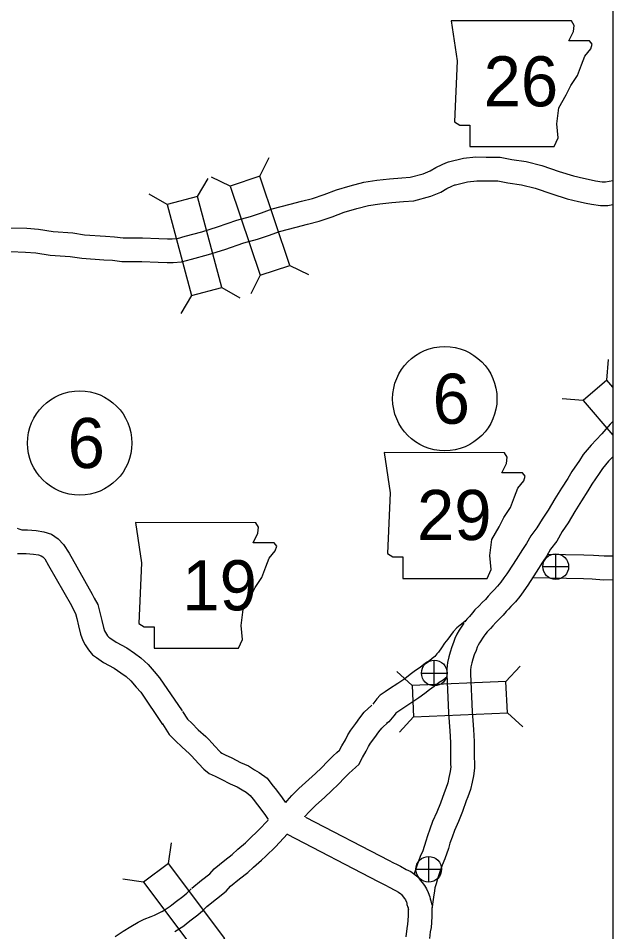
# Model space of a CAD drawing. Extents: x 79818 to 83933, y 50884 to 53307.
# Drawn here: x 81359.7 to 81460, y 53002.4 to 53156.5 of the extents above; entities that cross this region are included whole.
import ezdxf

# ---------------------------------------------------------------- set-up
doc = ezdxf.new("R2010")
doc.units = 0
for name, color, linetype in [('Level 10', 7, 'Continuous'), ('Level 20', 7, 'Continuous'), ('Level 21', 7, 'Continuous'), ('Level 26', 7, 'Continuous'), ('Level 27', 7, 'Continuous'), ('R_No Plot', 7, 'Continuous')]:
    doc.layers.add(name, color=color, linetype=linetype)

msp = doc.modelspace()

# ---------------------------------------------------------------- linework, layer by layer
at = {"layer": 'Level 10'}
for points in [[(81358.49, 53121.12), (81361.17, 53121.03), (81363.16, 53120.89), (81365.61, 53120.48), (81368.95, 53120.24), (81370.9, 53119.95), (81374.45, 53119.7), (81375.97, 53119.61), (81377.43, 53119.42), (81380.66, 53119.42), (81383.45, 53119.31), (81384.89, 53119.26), (81385.67, 53119.26), (81386.57, 53119.33), (81387.88, 53119.7), (81390.7, 53120.45), (81393.32, 53121.26), (81396.61, 53122.39), (81398.9, 53123.02), (81400.76, 53123.65), (81402.56, 53124.32), (81405.57, 53125.09), (81407.48, 53125.59), (81409.36, 53126.08), (81411.33, 53126.74), (81413.4, 53127.52), (81415.72, 53128.22), (81418, 53128.8), (81420.19, 53129.14), (81422.31, 53129.39), (81424.4, 53129.56), (81425.81, 53129.64), (81428, 53130.22), (81429.18, 53130.72), (81430.16, 53131.31), (81431.22, 53131.79), (81431.84, 53132.07), (81432.28, 53132.23), (81434.79, 53132.84), (81436.92, 53133.06), (81438.61, 53133.02), (81441, 53133.05), (81442.98, 53132.65), (81445.41, 53132.29), (81448.04, 53131.62), (81450.97, 53130.64), (81453.35, 53129.88), (81455.07, 53129.47), (81456.35, 53129.18), (81457.09, 53129.03), (81458.22, 53128.85), (81458.74, 53128.85), (81459.98, 53129.09)], [(81358.44, 53117.12), (81360.96, 53117.03), (81362.7, 53116.92), (81365.13, 53116.51), (81368.51, 53116.27), (81370.46, 53115.97), (81374.19, 53115.71), (81375.6, 53115.63), (81377.18, 53115.42), (81380.58, 53115.42), (81383.3, 53115.31), (81384.82, 53115.26), (81385.83, 53115.26), (81387.27, 53115.38), (81388.93, 53115.84), (81391.8, 53116.6), (81394.56, 53117.46), (81397.8, 53118.57), (81400.07, 53119.2), (81402.09, 53119.88), (81403.76, 53120.5), (81406.57, 53121.22), (81408.49, 53121.72), (81410.5, 53122.24), (81412.67, 53122.97), (81414.69, 53123.73), (81416.8, 53124.37), (81418.8, 53124.88), (81420.73, 53125.18), (81422.71, 53125.41), (81424.68, 53125.57), (81426.44, 53125.67), (81429.29, 53126.43), (81431, 53127.14), (81432.03, 53127.77), (81432.86, 53128.14), (81433.34, 53128.36), (81433.44, 53128.39), (81435.47, 53128.88), (81437.09, 53129.05), (81438.59, 53129.02), (81440.63, 53129.05), (81442.28, 53128.71), (81444.62, 53128.36), (81446.91, 53127.78), (81449.73, 53126.83), (81452.27, 53126.02), (81454.18, 53125.57), (81455.52, 53125.27), (81456.38, 53125.09), (81457.89, 53124.85), (81459.13, 53124.85), (81459.98, 53125.02)], [(81459.98, 53088.43), (81459.57, 53088.02), (81458.14, 53086.34), (81457.2, 53085.35), (81456.32, 53084.44), (81455.02, 53082.9), (81454.36, 53081.87), (81453.1, 53080.02), (81452.39, 53078.84), (81451.36, 53077.18), (81450.21, 53075.39), (81449.07, 53073.48), (81448.07, 53071.99), (81447.2, 53070.5), (81446.16, 53069.13), (81445.45, 53067.89), (81444.78, 53066.86), (81443.7, 53065.17)], [(81459.98, 53082.47), (81459.28, 53081.75), (81458.25, 53080.52), (81457.7, 53079.67), (81456.47, 53077.86), (81455.8, 53076.75), (81454.74, 53075.04), (81453.61, 53073.28), (81452.45, 53071.34), (81451.46, 53069.87), (81450.53, 53068.27), (81449.5, 53066.92), (81448.86, 53065.8), (81448.14, 53064.69), (81447.07, 53063.02)], [(81359.57, 53070.45), (81359.85, 53070.34), (81360.33, 53070.18), (81361.28, 53070.15), (81362.75, 53070.04), (81364.03, 53069.85), (81365.32, 53069.43), (81366.48, 53068.67), (81367.39, 53067.7), (81368.3, 53066.21), (81372.21, 53059.29), (81372.55, 53058.64), (81373.14, 53057.55), (81373.48, 53056.23), (81373.82, 53054.9), (81374.08, 53053.69), (81374.28, 53053.14), (81374.45, 53052.83), (81374.8, 53052.3), (81374.98, 53052.08), (81375.16, 53051.96), (81376.23, 53051.22), (81378.02, 53050.25), (81379.32, 53049.34), (81380.43, 53048.56), (81381.62, 53047.46), (81382.65, 53046.26), (81383.57, 53045.23), (81387.39, 53039.61)], [(81359.62, 53066.2), (81361.06, 53066.15), (81362.32, 53066.06), (81363.12, 53065.94), (81363.57, 53065.8), (81363.88, 53065.59), (81364.19, 53065.26), (81364.85, 53064.18), (81368.69, 53057.39), (81369.01, 53056.77), (81369.39, 53056.06), (81369.61, 53055.24), (81369.92, 53054), (81370.23, 53052.57), (81370.62, 53051.5), (81371, 53050.78), (81371.57, 53049.93), (81372.26, 53049.07), (81372.94, 53048.63), (81374.13, 53047.8), (81375.92, 53046.84), (81377.02, 53046.07), (81377.92, 53045.43), (81378.74, 53044.68), (81379.64, 53043.63), (81380.41, 53042.76), (81384.08, 53037.36)], [(81443.71, 53065.19), (81442.32, 53063.07), (81442.1, 53062.74), (81441.61, 53062.05), (81441.09, 53061.32), (81440.57, 53060.66), (81439.99, 53060.06), (81439.52, 53059.61), (81438.96, 53058.99), (81438.51, 53058.42), (81437.99, 53057.91), (81437.43, 53057.36), (81436.75, 53056.65), (81436.32, 53056.14), (81435.82, 53055.57), (81435.4, 53055.08), (81435.02, 53054.64)], [(81459.98, 53065.75), (81458.51, 53065.7), (81456.73, 53065.86), (81455.11, 53065.88), (81448.91, 53066.02)], [(81447.06, 53063), (81445.65, 53060.84), (81445.38, 53060.45), (81444.87, 53059.73), (81444.3, 53058.93), (81443.6, 53058.03), (81442.81, 53057.22), (81442.39, 53056.81), (81442.01, 53056.4), (81441.51, 53055.76), (81440.79, 53055.05), (81440.27, 53054.55), (81439.74, 53053.98), (81439.35, 53053.53), (81438.83, 53052.94), (81438.44, 53052.48), (81438.06, 53052.03)], [(81459.98, 53061.75), (81458.4, 53061.69), (81456.53, 53061.86), (81455.04, 53061.88), (81446.45, 53062.07)], [(81435.34, 53054.93), (81434.23, 53054.1), (81433.7, 53053.61), (81433.09, 53052.96), (81432.62, 53052.36), (81432.16, 53051.73), (81431.6, 53051.07), (81431.13, 53050.28), (81430.62, 53049.55), (81430.31, 53049.23), (81429.97, 53048.83), (81429.51, 53048.44), (81429.07, 53048.08), (81428.4, 53047.67), (81427.51, 53046.96), (81426.74, 53046.45), (81425.84, 53045.75), (81424.94, 53045.06), (81423.75, 53044.27), (81422.32, 53043.35), (81421.61, 53042.85), (81420.78, 53042.29), (81420.18, 53041.64), (81419.87, 53041.22), (81419.5, 53040.76)], [(81434.86, 53054.42), (81434.09, 53053.22), (81433.7, 53052.56), (81433.38, 53051.86), (81433.15, 53051.16), (81432.87, 53050.42), (81432.57, 53049.52), (81432.36, 53048.77), (81432.12, 53047.78), (81431.99, 53046.68), (81432, 53045.79), (81432.28, 53039.3)], [(81438.22, 53052.25), (81437.5, 53051.13), (81437.26, 53050.72), (81437.11, 53050.4), (81436.93, 53049.84), (81436.64, 53049.08), (81436.4, 53048.34), (81436.23, 53047.75), (81436.06, 53047.08), (81436, 53046.48), (81436, 53045.9), (81436.28, 53039.47)], [(81432.06, 53045.36), (81432.06, 53045.36), (81431.41, 53044.82), (81430.7, 53044.39), (81429.86, 53043.72), (81429.07, 53043.19), (81428.28, 53042.58), (81427.27, 53041.81), (81425.93, 53040.92), (81424.56, 53040.04), (81423.89, 53039.56), (81423.4, 53039.23), (81423.27, 53039.09), (81423.05, 53038.79), (81422.24, 53037.79), (81421.84, 53037.52)], [(81404.83, 53024.15), (81405.08, 53024.44), (81405.89, 53025.34), (81407.06, 53026.54), (81408.74, 53028.05), (81409.85, 53029.04), (81410.87, 53030.04), (81411.87, 53031.11), (81412.81, 53032.06), (81413.44, 53032.59), (81413.91, 53033.02), (81413.92, 53033.02), (81414.32, 53033.74), (81414.9, 53034.75), (81415.33, 53035.58), (81415.82, 53036.4), (81416.65, 53037.5), (81417.32, 53038.46), (81418.06, 53039.39), (81419.33, 53040.61)], [(81387.43, 53039.55), (81388.27, 53038.21), (81388.99, 53037.55), (81390.09, 53036.45), (81391.37, 53035.33), (81391.89, 53034.78), (81392.38, 53034.23), (81392.92, 53033.64), (81393.68, 53032.85), (81393.82, 53032.68), (81394.06, 53032.51), (81394.65, 53032.21), (81395.73, 53031.72), (81397.23, 53030.92), (81398.55, 53030.34), (81399.55, 53029.71), (81400.35, 53029.24), (81401.69, 53028.27), (81402.51, 53027.19), (81403.27, 53026.23), (81404.24, 53024.94), (81404.73, 53024.22), (81404.75, 53024.18)], [(81432.29, 53039.23), (81432.52, 53036.24), (81432.61, 53034.3), (81432.64, 53033.39), (81432.63, 53031.98), (81432.65, 53030.56), (81432.66, 53030.2), (81432.54, 53029.38), (81432.34, 53028.41), (81432.16, 53027.47), (81431.81, 53026.55), (81431.53, 53025.8), (81430.92, 53024.07), (81430.31, 53022.54), (81429.61, 53020.97), (81429.11, 53019.69), (81428.72, 53018.53), (81428.44, 53017.63), (81427.93, 53016.05), (81427.52, 53015.06), (81426.92, 53013.47), (81426.58, 53012.46), (81426.48, 53012.1)], [(81436.27, 53039.54), (81436.51, 53036.49), (81436.6, 53034.45), (81436.64, 53033.44), (81436.63, 53032.01), (81436.65, 53030.63), (81436.67, 53029.94), (81436.48, 53028.68), (81436.26, 53027.63), (81436.02, 53026.38), (81435.55, 53025.14), (81435.29, 53024.43), (81434.66, 53022.67), (81433.99, 53020.98), (81433.31, 53019.44), (81432.88, 53018.32), (81432.53, 53017.3), (81432.26, 53016.41), (81431.68, 53014.66), (81431.24, 53013.6), (81430.69, 53012.13), (81430.41, 53011.3), (81430.18, 53010.44), (81429.98, 53009.77), (81429.91, 53009.25), (81429.78, 53008.21), (81429.46, 53006.18)], [(81384.04, 53037.42), (81385.17, 53035.62), (81386.22, 53034.66), (81387.35, 53033.53), (81388.58, 53032.46), (81388.94, 53032.07), (81390.12, 53030.76), (81391.02, 53029.78), (81391.95, 53029.09), (81392.93, 53028.6), (81393.97, 53028.13), (81395.47, 53027.33), (81396.67, 53026.8), (81397.47, 53026.29), (81398.16, 53025.89), (81398.86, 53025.37), (81399.35, 53024.73), (81400.1, 53023.78), (81400.98, 53022.62), (81401.41, 53021.97), (81401.89, 53021.28)], [(81408.05, 53021.76), (81408.08, 53021.8), (81408.8, 53022.6), (81409.83, 53023.65), (81411.41, 53025.07), (81412.58, 53026.12), (81413.73, 53027.24), (81414.76, 53028.34), (81415.51, 53029.11), (81416.06, 53029.56), (81416.66, 53030.11), (81417.14, 53030.58), (81417.8, 53031.78), (81418.41, 53032.84), (81418.82, 53033.63), (81419.14, 53034.16), (81419.88, 53035.14), (81420.53, 53036.07), (81421.03, 53036.7), (81422.1, 53037.72)], [(81389.01, 53009.71), (81390.65, 53011.06), (81392.04, 53012.15), (81392.76, 53012.96), (81394.55, 53014.42), (81395.83, 53015.4), (81396.77, 53016.28), (81398.05, 53017.36), (81398.69, 53018), (81400.27, 53019.52), (81401.86, 53021.21)], [(81408.16, 53021.71), (81422.3, 53014.41), (81422.92, 53014.07), (81423.65, 53013.73), (81424.18, 53013.42), (81425.14, 53012.89), (81425.94, 53012.52), (81427.13, 53011.64), (81427.52, 53011.1), (81427.83, 53010.7), (81428.21, 53010.2), (81428.55, 53009.64), (81428.85, 53009.01), (81429.16, 53008.26), (81429.2, 53007.91), (81429.32, 53007.56), (81429.45, 53006.84)], [(81391.54, 53006.62), (81393.15, 53007.94), (81394.79, 53009.23), (81395.53, 53010.06), (81397.04, 53011.28), (81398.42, 53012.35), (81399.42, 53013.28), (81400.76, 53014.42), (81401.49, 53015.15), (81403.11, 53016.7), (81405.16, 53018.88)], [(81405.06, 53018.81), (81420.43, 53010.87), (81421.12, 53010.5), (81421.79, 53010.18), (81422.19, 53009.95), (81423.33, 53009.32), (81423.88, 53009.06), (81424.26, 53008.78), (81424.34, 53008.68), (81424.66, 53008.27), (81424.89, 53007.96), (81425.02, 53007.74), (81425.19, 53007.38), (81425.25, 53007.24), (81425.28, 53006.98), (81425.45, 53006.53), (81425.52, 53006.12)], [(81383.99, 53005.8), (81385.35, 53006.67), (81385.64, 53006.89), (81386.39, 53007.51), (81387.5, 53008.33), (81388.15, 53008.9), (81388.9, 53009.62)], [(81386.14, 53002.43), (81387.63, 53003.38), (81388.11, 53003.74), (81388.87, 53004.36), (81390.02, 53005.22), (81390.84, 53005.95), (81391.65, 53006.72)], [(81425.49, 53006.48), (81425.49, 53005.11), (81425.43, 53004.25), (81425.37, 53003.63), (81425.24, 53002.92), (81425.11, 53001.5)], [(81429.49, 53006.48), (81429.49, 53004.99), (81429.42, 53003.93), (81429.34, 53003.08), (81429.21, 53002.38), (81429.1, 53001.21)], [(81376.07, 53001.58), (81377.43, 53002.48), (81378.7, 53003.26), (81379.93, 53003.98), (81380.97, 53004.49), (81382.14, 53004.92), (81382.68, 53005.16), (81384.17, 53005.9)]]:
    msp.add_lwpolyline(points, dxfattribs=at)
at = {"layer": 'Level 20'}
for p, q in [((81400.48, 53129.8), (81402.05, 53132.95)), ((81395.48, 53128.12), (81392.32, 53129.68)), ((81389.97, 53126.38), (81391.73, 53129.43)), ((81384.86, 53125.02), (81381.82, 53126.79)), ((81405.53, 53114.78), (81408.68, 53113.22)), ((81400.52, 53113.1), (81398.96, 53109.95)), ((81388.93, 53109.72), (81387.17, 53106.67)), ((81394.04, 53111.07), (81397.08, 53109.31)), ((81458.99, 53095.41), (81459.27, 53098.92)), ((81454.97, 53091.98), (81451.47, 53092.26)), ((81441.98, 53044.58), (81444.36, 53047.18)), ((81426.16, 53043.91), (81423.57, 53046.29)), ((81442.21, 53039.31), (81444.8, 53036.93)), ((81426.38, 53038.63), (81424, 53036.04)), ((81385.06, 53013.91), (81385.56, 53017.39)), ((81380.83, 53010.74), (81377.35, 53011.24))]:
    msp.add_line(p, q, dxfattribs=at)
for points in [[(81395.48, 53128.12), (81400.52, 53113.1), (81405.53, 53114.78), (81400.48, 53129.8)], [(81394.04, 53111.07), (81389.97, 53126.38), (81384.86, 53125.02), (81388.93, 53109.72)], [(81441.98, 53044.58), (81426.16, 53043.91), (81426.38, 53038.63), (81442.21, 53039.31)], [(81394.56, 53001.23), (81385.06, 53013.91), (81380.83, 53010.74), (81390.34, 52998.06)]]:
    msp.add_lwpolyline(points, close=True, dxfattribs=at)
msp.add_lwpolyline([(81459.98, 53094.25), (81458.99, 53095.41), (81454.97, 53091.98), (81459.98, 53086.12)], dxfattribs=at)
at = {"layer": 'Level 21'}
for points in [[(81432.72, 53156.05), (81433.74, 53149.28), (81433.29, 53139.01), (81434.19, 53138.45), (81435.88, 53138.45), (81435.88, 53134.84), (81450.09, 53134.84), (81450.77, 53136.31), (81450.54, 53138.68), (81450.88, 53141.38), (81452.12, 53143.53), (81452.91, 53145.11), (81454.04, 53146.8), (81454.72, 53148.6), (81455.28, 53150.07), (81456.29, 53151.31), (81456.52, 53152.1), (81456.07, 53152.66), (81452.57, 53152.66), (81453.36, 53154.24), (81453.47, 53155.26), (81453.01, 53156.04)], [(81421.44, 53083.19), (81422.45, 53076.42), (81422, 53066.15), (81422.91, 53065.59), (81424.6, 53065.59), (81424.6, 53061.98), (81438.81, 53061.98), (81439.49, 53063.45), (81439.26, 53065.82), (81439.6, 53068.52), (81440.84, 53070.67), (81441.63, 53072.25), (81442.76, 53073.94), (81443.43, 53075.74), (81444, 53077.21), (81445.01, 53078.45), (81445.24, 53079.24), (81444.79, 53079.8), (81441.29, 53079.8), (81442.08, 53081.38), (81442.19, 53082.4), (81441.72, 53083.18)], [(81379.51, 53071.38), (81380.53, 53064.62), (81380.08, 53054.35), (81380.98, 53053.79), (81382.67, 53053.79), (81382.67, 53050.18), (81396.88, 53050.18), (81397.56, 53051.65), (81397.33, 53054.02), (81397.67, 53056.72), (81398.91, 53058.87), (81399.7, 53060.44), (81400.83, 53062.14), (81401.5, 53063.94), (81402.07, 53065.41), (81403.08, 53066.65), (81403.31, 53067.44), (81402.86, 53068), (81399.36, 53068), (81400.15, 53069.58), (81400.26, 53070.6), (81399.8, 53071.37)]]:
    msp.add_lwpolyline(points, close=True, dxfattribs=at)
at = {"layer": 'Level 26'}
for p, q in [((81450.37, 53061.79), (81450.37, 53066.12)), ((81448.21, 53063.96), (81452.54, 53063.96)), ((81429.89, 53043.84), (81429.89, 53048.17)), ((81427.72, 53046.01), (81432.06, 53046.01)), ((81428.95, 53010.75), (81428.95, 53015.08)), ((81426.78, 53012.91), (81431.12, 53012.91))]:
    msp.add_line(p, q, dxfattribs=at)
for centre in [(81450.37, 53063.96), (81429.89, 53046.01), (81428.95, 53012.91)]:
    msp.add_circle(centre, 2.17, dxfattribs=at)
at = {"layer": 'Level 27'}
for centre in [(81431.66, 53092.29), (81370.1, 53084.81)]:
    msp.add_circle(centre, 8.8, dxfattribs=at)
at = {"layer": 'R_No Plot'}
msp.add_lwpolyline([(80798.6, 53193.52), (81459.98, 53193.52), (81459.98, 52610.7), (80798.6, 52610.7)], close=True, dxfattribs=at)
msp.add_lwpolyline([(80798.6, 53193.52), (81459.98, 53193.52), (81459.98, 52610.7), (80798.6, 52610.7)], close=True, dxfattribs=at)

# ---------------------------------------------------------------- texts
at = {"layer": 'Level 21'}
for s, p in [('26', (81438.21, 53141.6)), ('29', (81426.98, 53068.45)), ('19', (81387.41, 53056.59))]:
    msp.add_text(s, height=8.448, dxfattribs=at).set_placement(p)
at = {"layer": 'Level 27'}
for p in [(81429.61, 53088.06), (81368.05, 53080.59)]:
    msp.add_text('6', height=8.45, dxfattribs=at).set_placement(p)

doc.saveas('drawing.dxf')
